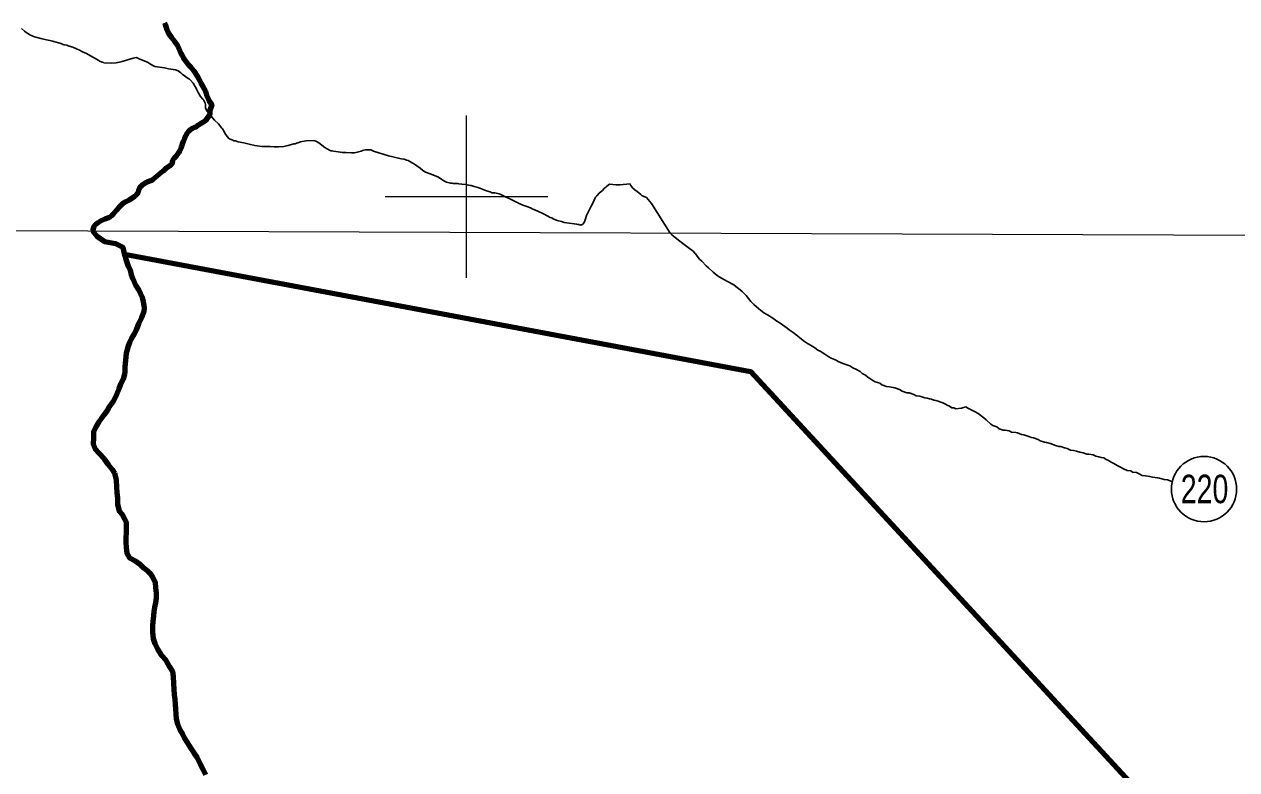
# Model space of a CAD drawing. Extents: x 553962 to 842807, y 8883888 to 9032388.
# Drawn here: x 644560 to 659476, y 8942952 to 8952120 of the extents above; entities that cross this region are included whole.
import ezdxf
from ezdxf.enums import TextEntityAlignment as Align

# ---------------------------------------------------------------- set-up
doc = ezdxf.new("R2010")
doc.units = 0
doc.header["$LTSCALE"] = 200
for name, color, linetype, lineweight in [('1', 7, 'Continuous', 13), ('12', 7, 'Continuous', 25), ('2', 7, 'Continuous', 13), ('24', 7, 'Continuous', 25), ('48', 7, 'Continuous', 25), ('9', 7, 'Continuous', 90)]:
    doc.layers.add(name, color=color, linetype=linetype, lineweight=lineweight)

msp = doc.modelspace()

# ---------------------------------------------------------------- linework, layer by layer
at = {"layer": '1'}
msp.add_line((565315.3, 8949866.8), (791497.7, 8949052.2), dxfattribs=at)
at = {"layer": '12'}
for points in [[(644525.6, 8952067.7), (644562.3, 8952035.3), (644585, 8952018.8), (644610.2, 8952003.3), (644630.2, 8951989.1), (644666.2, 8951972.1), (644686.9, 8951965), (644764.8, 8951944.4), (644796.3, 8951937.1)], [(644796.3, 8951937.1), (644909.5, 8951910.6), (644920.9, 8951908.3), (644925, 8951908), (644979.4, 8951891), (644998, 8951886), (645049.9, 8951868.9), (645083.2, 8951861.5), (645101.9, 8951853.7), (645139.4, 8951844.3), (645159.2, 8951837.9), (645204.5, 8951819), (645240.2, 8951802.2), (645277.4, 8951781.6), (645324.7, 8951759), (645344.3, 8951747.1), (645476.8, 8951676.5), (645486.1, 8951668), (645499.5, 8951664.1), (645517.2, 8951655.3), (645535.4, 8951649), (645539.2, 8951646.5), (645633, 8951642.2), (645691.3, 8951646.6), (645709.7, 8951650.6), (645730.5, 8951653.2), (645766.4, 8951661.2), (645899.9, 8951704.4), (645939.9, 8951711), (645983.5, 8951692.1)], [(645983.5, 8951692.1), (646075.3, 8951652.5), (646111.1, 8951629), (646148, 8951608.5), (646165.6, 8951600.8), (646285, 8951585.6), (646336.2, 8951574), (646420.6, 8951561.2), (646455.4, 8951547.2), (646471.8, 8951536), (646471.8, 8951536), (646486.8, 8951523.3), (646503.8, 8951505.7), (646575.7, 8951452.5), (646594.5, 8951444.4), (646606.7, 8951433.2), (646637.1, 8951396.7), (646646.8, 8951381.7), (646658, 8951359.9), (646668.8, 8951343), (646678.2, 8951321.5), (646688, 8951304.6), (646697.6, 8951280.8), (646727.3, 8951231.4), (646758, 8951198.7), (646768, 8951185.4), (646778.9, 8951166.6), (646784.6, 8951148.8), (646787.7, 8951132.6), (646791.2, 8951093), (646800.1, 8951065.2), (646806.8, 8951054.1), (646825.7, 8951029.2), (646836.3, 8951019.3)], [(646836.3, 8951019.3), (646900.5, 8950941.1), (646947.8, 8950893.8), (646989, 8950843.2), (646999.3, 8950832.7), (647020.7, 8950801.7), (647029.2, 8950781.7), (647056, 8950740.5), (647082.1, 8950712.4), (647088.1, 8950711.7), (647092.4, 8950707.5), (647124.6, 8950692.9), (647140, 8950688.1), (647158.6, 8950685.3), (647192, 8950676), (647261.7, 8950661.8), (647311.3, 8950649.3), (647341.4, 8950639.7), (647378.7, 8950633.5), (647398.1, 8950627.8), (647482.5, 8950615.3), (647499.6, 8950617.1), (647516.6, 8950616.2), (647534.4, 8950617.1), (647567, 8950615.2), (647584.8, 8950616), (647635.2, 8950612), (647686.3, 8950610.9), (647752.8, 8950616), (647787.8, 8950625.3), (647806.4, 8950629), (647874.6, 8950648.1), (647891.6, 8950651.4), (647907.9, 8950657.4), (647927.3, 8950661.4), (647959.8, 8950672.6), (647976.9, 8950676.8), (648028, 8950685.3), (648114.8, 8950689.6), (648132.7, 8950687.8), (648148.1, 8950682.9)], [(648148.1, 8950682.9), (648164.7, 8950675), (648182.5, 8950661), (648182.5, 8950661), (648220.1, 8950634.8), (648256.1, 8950605.6), (648313.6, 8950571.5), (648330.6, 8950564.1), (648347.6, 8950561.8), (648365.5, 8950557.5), (648449.1, 8950549.1), (648469.5, 8950544.6), (648518.1, 8950542.6), (648584.7, 8950537.4), (648618.8, 8950538.4), (648656, 8950545.3), (648704, 8950560.3), (648722.7, 8950568.1), (648755.2, 8950574.3), (648790.8, 8950577.7), (648823.9, 8950574.6), (648830.2, 8950570.4), (648856.3, 8950558.2), (649040.7, 8950501.6), (649162.3, 8950475.3), (649195.7, 8950466.1), (649232.2, 8950461.1), (649246.8, 8950457.3), (649263.9, 8950450), (649281.7, 8950444.2), (649302.8, 8950433.5), (649338.4, 8950412.6), (649353.4, 8950402.1), (649372.5, 8950392.3), (649390.3, 8950378.1), (649429.6, 8950352.4), (649463.8, 8950322.8)], [(649463.8, 8950322.8), (649496, 8950302.2), (649566.4, 8950276.3), (649656.2, 8950238.2), (649697.2, 8950209.8), (649723.5, 8950193.7), (649754.2, 8950177.4), (649803.5, 8950168), (649822.1, 8950166.5), (649838.4, 8950163.6), (649890.3, 8950161.1), (649908.1, 8950157), (649941.4, 8950154.8), (649991, 8950148.7), (650043.7, 8950137.9), (650060, 8950135.7), (650094.1, 8950124.2), (650129.7, 8950116.2), (650163, 8950105.8), (650246.8, 8950073.4), (650290.2, 8950059), (650299.6, 8950053.7), (650314, 8950049.1), (650350.6, 8950046.1), (650401.7, 8950034.4), (650423.7, 8950025.5), (650495.5, 8949988.7), (650527.2, 8949975.8), (650567.9, 8949956.7), (650647.1, 8949916), (650692.9, 8949894.2), (650744.7, 8949878.8), (650786.2, 8949862.9), (650817.8, 8949847.6), (650868.1, 8949827.7), (650955.7, 8949785.1), (651029.6, 8949745.1), (651050.4, 8949738.1), (651068, 8949728), (651116.1, 8949708.1), (651168, 8949695.8), (651202.9, 8949684), (651236.2, 8949676.7), (651354.7, 8949662.8), (651372.6, 8949657.6), (651386.2, 8949655.9), (651395.9, 8949651.2), (651408.9, 8949652.2), (651421.4, 8949655), (651431.1, 8949662), (651447.1, 8949681.5), (651460.4, 8949714.1), (651478.1, 8949766.7), (651536.2, 8949883), (651545, 8949904.7), (651589.1, 8949992.5), (651602.4, 8950009.9), (651633.8, 8950042.4), (651659.3, 8950063.8), (651672.2, 8950077.6), (651695.1, 8950098.5), (651713.6, 8950118.7), (651719.4, 8950120.8), (651727.6, 8950129), (651743.7, 8950140.7)], [(651743.7, 8950140.7), (651759.9, 8950152.4), (651841.5, 8950147.5), (651886.8, 8950146.4), (652015.9, 8950156.6)], [(652015.9, 8950156.6), (652017.2, 8950142.2), (652048.2, 8950106.5), (652073.3, 8950084.6), (652100.6, 8950064.8), (652145.1, 8950025.5), (652162.5, 8950012.1), (652213.7, 8949988.4), (652275.7, 8949914.2), (652507.9, 8949552.8)], [(652507.9, 8949552.8), (652526.9, 8949530.3), (652569.2, 8949497.5), (652626.3, 8949452.1), (652693.5, 8949399.1), (652728.3, 8949373.8), (652790.5, 8949328.3), (652815.3, 8949300.6), (652867.3, 8949232.7), (652894.6, 8949204.9), (652949.2, 8949149.5), (652979, 8949124.3), (653033.6, 8949071.3), (653085.8, 8949030.9), (653110.7, 8949013.2), (653173, 8948977.8), (653212.8, 8948957.5), (653287.6, 8948916.9), (653314.9, 8948894.2), (653367.1, 8948853.8), (653392, 8948833.6), (653441.6, 8948785.7)], [(653441.6, 8948785.7), (653498.6, 8948710.3), (653535.8, 8948672.5), (653595.5, 8948622), (653660.1, 8948571.5), (653702.4, 8948546.2), (653779.6, 8948498.1), (653804.4, 8948477.9), (653859.2, 8948442.5), (653889.1, 8948422.3), (653946.3, 8948381.8), (653971.1, 8948361.6), (654018.4, 8948328.8), (654070.6, 8948288.4), (654100.4, 8948263.2), (654160.1, 8948220.2), (654195, 8948194.9), (654262.2, 8948156.9), (654284.6, 8948141.8), (654324.4, 8948114), (654351.8, 8948098.8), (654409.1, 8948063.3), (654458.8, 8948030.5), (654488.7, 8948015.2), (654548.5, 8947987.3), (654573.4, 8947972.1), (654628.3, 8947946.7), (654655.7, 8947941.5), (654718.1, 8947918.6), (654752.9, 8947893.3), (654800.3, 8947875.5), (654842.6, 8947850.2), (654867.5, 8947825), (654909.8, 8947804.7), (654937.1, 8947779.4), (654999.3, 8947739), (655026.8, 8947723.8), (655084.1, 8947705.9), (655111.5, 8947685.7), (655168.9, 8947665.2), (655203.9, 8947662.5), (655268.8, 8947647.1), (655328.6, 8947626.6), (655358.5, 8947606.4), (655415.9, 8947588.5), (655445.9, 8947588.3), (655505.8, 8947565.4), (655533.2, 8947550.2), (655578.2, 8947547.4), (655600.6, 8947539.7), (655640.5, 8947524.4), (655668, 8947521.8), (655698, 8947514), (655720.4, 8947511.4), (655747.8, 8947496.2), (655772.8, 8947493.5), (655802.8, 8947483.3), (655835.2, 8947473.1), (655860.1, 8947462.9), (655892.6, 8947450.2), (655915, 8947435), (655942.4, 8947424.8), (655969.7, 8947404.6), (655997.2, 8947401.9), (656019.7, 8947391.7), (656089.8, 8947398.8)], [(656089.8, 8947398.8), (656144.9, 8947413.4), (656177.2, 8947393.2), (656259.5, 8947355.1), (656294.3, 8947332.3), (656364, 8947281.8), (656393.8, 8947254.1), (656450.9, 8947201.1), (656475.8, 8947185.9), (656523.2, 8947168.1), (656553, 8947145.4), (656602.9, 8947127.5), (656627.9, 8947127.3), (656675.4, 8947119.5), (656705.3, 8947104.3), (656757.8, 8947101.5), (656780.2, 8947093.8), (656830.1, 8947073.4), (656857.6, 8947070.8), (656907.5, 8947055.4), (656952.4, 8947040.1), (656977.4, 8947034.9), (657032.2, 8947012), (657059.6, 8946996.8), (657112, 8946978.9), (657137, 8946978.8), (657199.4, 8946960.8), (657234.3, 8946943.1), (657289.2, 8946927.7), (657311.7, 8946927.6), (657356.6, 8946912.2), (657391.6, 8946904.5), (657431.4, 8946884.2), (657466.4, 8946879), (657506.4, 8946871.2), (657546.3, 8946858.4), (657586.2, 8946850.6), (657631.1, 8946835.3), (657656.1, 8946832.6), (657708.6, 8946824.8), (657741, 8946807.1), (657781, 8946801.8), (657808.4, 8946794.1), (657840.9, 8946788.9), (657868.2, 8946768.7), (657898.1, 8946753.4), (657930.5, 8946735.7), (657965.4, 8946717.9), (658005.2, 8946692.6), (658045.1, 8946672.3), (658085, 8946652.1), (658129.8, 8946634.2), (658172.3, 8946628.9), (658194.7, 8946611.3), (658242.2, 8946608.4), (658277.1, 8946590.7), (658314.5, 8946572.9), (658354.4, 8946567.7), (658406.9, 8946559.8), (658439.3, 8946552.1), (658501.8, 8946544.2), (658524.3, 8946536.5), (658556.7, 8946531.3), (658581.7, 8946523.6), (658624.1, 8946515.8), (658678.1, 8946495.9)]]:
    msp.add_lwpolyline(points, dxfattribs=at)
at = {"layer": '2'}
for p, q in [((650000, 8949000), (650000, 8951000)), ((649000, 8950000), (651000, 8950000))]:
    msp.add_line(p, q, dxfattribs=at)
at = {"layer": '24', "lineweight": 53}
for points in [[(646283.8, 8952137.9), (646294.2, 8952117.2), (646303.6, 8952093.2), (646314.2, 8952051.4), (646322.1, 8952031.6), (646333.3, 8952009.5), (646371.8, 8951955.7), (646409.8, 8951910.5), (646439.8, 8951866.6), (646450.5, 8951847.3), (646458, 8951830.6), (646472.5, 8951791.1), (646486.6, 8951759.9), (646498.1, 8951747.5), (646499.4, 8951739.7), (646505.1, 8951731.6), (646514.5, 8951713), (646583.4, 8951618.5), (646609.2, 8951590.9), (646641.2, 8951551.7), (646693.7, 8951470.3), (646714.7, 8951432.5), (646733, 8951394), (646757.5, 8951355.4), (646787.6, 8951297.6), (646794.5, 8951277.6), (646802.9, 8951258.2), (646813.5, 8951223.4), (646828.6, 8951181.9), (646867.6, 8951129.6), (646843.9, 8951061.1), (646845, 8951008.9), (646791.1, 8950934.1), (646683.1, 8950866.1), (646677.6, 8950858.9), (646671.1, 8950853.6), (646653.5, 8950848.9), (646638.2, 8950843.1), (646630.5, 8950838.5), (646616.1, 8950832.7), (646599.8, 8950823.2), (646580.2, 8950802.2), (646561.5, 8950775.5), (646560.4, 8950771.5), (646555.5, 8950768.2), (646542.3, 8950744.3), (646531.8, 8950710), (646515, 8950677.7), (646512.5, 8950667.1), (646506.4, 8950657.3), (646501.5, 8950645.9), (646497.6, 8950630.7), (646492.6, 8950619.9), (646490.9, 8950607.9), (646484.9, 8950590.5), (646469.4, 8950559.1), (646462.5, 8950548.1), (646458, 8950536.5), (646432.8, 8950502.7), (646402.4, 8950473.1), (646389.6, 8950454.9), (646380.3, 8950433.1), (646383.9, 8950415.2), (646358.3, 8950385.9), (646349.6, 8950380.1), (646346.8, 8950375.3), (646301.4, 8950345.1), (646282.4, 8950327.6), (646263.6, 8950315.1), (646191.8, 8950251), (646140.7, 8950210.9), (646124.2, 8950199.9), (646066.5, 8950178.1), (646011.5, 8950140), (645996.7, 8950128.3), (645982.6, 8950114.3), (645972, 8950100.3), (645964.6, 8950078.7), (645959.7, 8950055.9), (645950.6, 8950035.7), (645935.3, 8950018), (645917.5, 8950001), (645852.5, 8949956.4), (645811.5, 8949936.1), (645770.2, 8949910.8), (645755.5, 8949898), (645724.3, 8949866.7), (645691.2, 8949830.5), (645653.7, 8949784.5), (645634.4, 8949765.2), (645614.7, 8949747.7), (645596.6, 8949739.8), (645549.2, 8949723.6), (645488.8, 8949693.4), (645467.8, 8949680.1), (645433.2, 8949653.7), (645415.9, 8949633.6), (645398.8, 8949579.9)], [(645398.8, 8949579.9), (645451.4, 8949513.8), (645546.2, 8949449.6), (645683.8, 8949425.1), (645771.3, 8949377.1), (645790.9, 8949299.5), (645808.1, 8949229.4), (645840.2, 8949144.1), (645862.5, 8949099), (645877.2, 8949041.4), (645894.5, 8948988.8), (645929.2, 8948913.5), (645968.9, 8948848.3), (645990.2, 8948804.6)], [(645990.2, 8948804.6), (646010.9, 8948758.1), (646021.2, 8948711.7), (646036.8, 8948634.2), (646031.6, 8948582.6), (646000.6, 8948510.3), (645964.4, 8948438), (645936.5, 8948358.1), (645911.3, 8948313.2), (645873.5, 8948253.4), (645853.2, 8948208.5), (645832.9, 8948151), (645815.1, 8948076.1), (645807.1, 8947983.6), (645799.2, 8947908.6), (645796.4, 8947834.9)], [(645796.4, 8947834.9), (645776, 8947756.1), (645745.7, 8947693.7), (645725.4, 8947636.3), (645695.1, 8947568.9), (645674.8, 8947521.4), (645649.6, 8947474), (645596.7, 8947399.3), (645571.5, 8947356.9), (645541.2, 8947317), (645511, 8947272.1), (645475.8, 8947229.8), (645437.9, 8947162.4), (645412.7, 8947110), (645409.8, 8947032.5), (645409.4, 8946954.9), (645431.6, 8946894.8), (645476.4, 8946847), (645541.1, 8946774.1), (645593.3, 8946706.3), (645643.1, 8946643.5), (645668.8, 8946601.4)], [(645668.8, 8946601.4), (645692.5, 8946518.2), (645694.6, 8946428.1), (645699.3, 8946363), (645706.4, 8946292.9), (645706.1, 8946220.4), (645728.2, 8946132.7), (645765.5, 8946092.5), (645792.8, 8946037.3), (645812.6, 8945992.2), (645814.8, 8945939.6), (645812, 8945874.6), (645809.1, 8945802.1), (645808.9, 8945752), (645813.6, 8945684.5), (645820.8, 8945616.9), (645855.5, 8945556.7), (645925.1, 8945520.2)], [(645925.1, 8945520.2), (645980.3, 8945480.9), (646030.3, 8945430.9), (646080.3, 8945396.3), (646111.1, 8945361.7), (646137.1, 8945322.6), (646171.8, 8945257.3), (646176.4, 8945189.8), (646181.1, 8945124.7), (646180.8, 8945062.1), (646173.1, 8945007.1), (646162.8, 8944947.2), (646155, 8944897.2), (646149.8, 8944847.1), (646141.9, 8944777.1), (646139.2, 8944722.1), (646138.8, 8944644.6), (646145.9, 8944567), (646168.2, 8944506.8), (646200.3, 8944434.1), (646247.5, 8944358.8), (646299.8, 8944301), (646309, 8944284.7)], [(646309, 8944284.7), (646346.9, 8944218.2), (646384.2, 8944160.4), (646391.3, 8944097.8), (646395.9, 8944012.8), (646398.1, 8943942.7), (646405.3, 8943872.6), (646412.5, 8943820), (646414.7, 8943755), (646419.5, 8943702.4), (646424.2, 8943637.3), (646428.9, 8943577.3), (646446.1, 8943512.1), (646475.8, 8943444.4), (646508, 8943389.2), (646527.8, 8943344.1), (646562.6, 8943288.9), (646604.8, 8943221.1), (646647, 8943160.8), (646684.3, 8943105.6), (646721.5, 8943027.8), (646756.1, 8942957.6), (646790.8, 8942889.9)]]:
    msp.add_lwpolyline(points, dxfattribs=at)
at = {"layer": '48'}
msp.add_circle((659073.8, 8946403.8), 401.3, dxfattribs=at)
at = {"layer": '9'}
for points in [[(646283.8, 8952137.9), (646294.2, 8952117.2), (646303.6, 8952093.2), (646314.2, 8952051.4), (646322.1, 8952031.6), (646333.3, 8952009.5), (646371.8, 8951955.7), (646409.8, 8951910.5), (646439.8, 8951866.6), (646450.5, 8951847.3), (646458, 8951830.6), (646472.5, 8951791.1), (646486.6, 8951759.9), (646498.1, 8951747.5), (646499.4, 8951739.7), (646505.1, 8951731.6), (646514.5, 8951713), (646583.4, 8951618.5), (646609.2, 8951590.9), (646641.2, 8951551.7), (646693.7, 8951470.3), (646714.7, 8951432.5), (646733, 8951394), (646757.5, 8951355.4), (646787.6, 8951297.6), (646794.5, 8951277.6), (646802.9, 8951258.2), (646813.5, 8951223.4), (646828.6, 8951181.9), (646867.6, 8951129.6), (646843.9, 8951061.1), (646845, 8951008.9), (646791.1, 8950934.1), (646683.1, 8950866.1), (646677.6, 8950858.9), (646671.1, 8950853.6), (646653.5, 8950848.9), (646638.2, 8950843.1), (646630.5, 8950838.5), (646616.1, 8950832.7), (646599.8, 8950823.2), (646580.2, 8950802.2), (646561.5, 8950775.5), (646560.4, 8950771.5), (646555.5, 8950768.2), (646542.3, 8950744.3), (646531.8, 8950710), (646515, 8950677.7), (646512.5, 8950667.1), (646506.4, 8950657.3), (646501.5, 8950645.9), (646497.6, 8950630.7), (646492.6, 8950619.9), (646490.9, 8950607.9), (646484.9, 8950590.5), (646469.4, 8950559.1), (646462.5, 8950548.1), (646458, 8950536.5), (646432.8, 8950502.7), (646402.4, 8950473.1), (646389.6, 8950454.9), (646380.3, 8950433.1), (646383.9, 8950415.2), (646358.3, 8950385.9), (646349.6, 8950380.1), (646346.8, 8950375.3), (646301.4, 8950345.1), (646282.4, 8950327.6), (646263.6, 8950315.1), (646191.8, 8950251), (646140.7, 8950210.9), (646124.2, 8950199.9), (646066.5, 8950178.1), (646011.5, 8950140), (645996.7, 8950128.3), (645982.6, 8950114.3), (645972, 8950100.3), (645964.6, 8950078.7), (645959.7, 8950055.9), (645950.6, 8950035.7), (645935.3, 8950018), (645917.5, 8950001), (645852.5, 8949956.4), (645811.5, 8949936.1), (645770.2, 8949910.8), (645755.5, 8949898), (645724.3, 8949866.7), (645691.2, 8949830.5), (645653.7, 8949784.5), (645634.4, 8949765.2), (645614.7, 8949747.7), (645596.6, 8949739.8), (645549.2, 8949723.6), (645488.8, 8949693.4), (645467.8, 8949680.1), (645433.2, 8949653.7), (645415.9, 8949633.6), (645398.8, 8949579.9)], [(645398.8, 8949579.9), (645451.4, 8949513.8), (645546.2, 8949449.6), (645683.8, 8949425.1), (645771.3, 8949377.1), (645790.9, 8949299.5), (645808.1, 8949229.4), (645840.2, 8949144.1), (645862.5, 8949099), (645877.2, 8949041.4), (645894.5, 8948988.8), (645929.2, 8948913.5), (645968.9, 8948848.3), (645990.2, 8948804.6)], [(645793.1, 8949290.9), (653495.4, 8947850), (659002.1, 8941889), (662654, 8939737.7), (668185.2, 8933928.8)], [(645990.2, 8948804.6), (646010.9, 8948758.1), (646021.2, 8948711.7), (646036.8, 8948634.2), (646031.6, 8948582.6), (646000.6, 8948510.3), (645964.4, 8948438), (645936.5, 8948358.1), (645911.3, 8948313.2), (645873.5, 8948253.4), (645853.2, 8948208.5), (645832.9, 8948151), (645815.1, 8948076.1), (645807.1, 8947983.6), (645799.2, 8947908.6), (645796.4, 8947834.9)], [(645796.4, 8947834.9), (645776, 8947756.1), (645745.7, 8947693.7), (645725.4, 8947636.3), (645695.1, 8947568.9), (645674.8, 8947521.4), (645649.6, 8947474), (645596.7, 8947399.3), (645571.5, 8947356.9), (645541.2, 8947317), (645511, 8947272.1), (645475.8, 8947229.8), (645437.9, 8947162.4), (645412.7, 8947110), (645409.8, 8947032.5), (645409.4, 8946954.9), (645431.6, 8946894.8), (645476.4, 8946847), (645541.1, 8946774.1), (645593.3, 8946706.3), (645643.1, 8946643.5), (645668.8, 8946601.4)], [(645668.8, 8946601.4), (645692.5, 8946518.2), (645694.6, 8946428.1), (645699.3, 8946363), (645706.4, 8946292.9), (645706.1, 8946220.4), (645728.2, 8946132.7), (645765.5, 8946092.5), (645792.8, 8946037.3), (645812.6, 8945992.2), (645814.8, 8945939.6), (645812, 8945874.6), (645809.1, 8945802.1), (645808.9, 8945752), (645813.6, 8945684.5), (645820.8, 8945616.9), (645855.5, 8945556.7), (645925.1, 8945520.2)], [(645925.1, 8945520.2), (645980.3, 8945480.9), (646030.3, 8945430.9), (646080.3, 8945396.3), (646111.1, 8945361.7), (646137.1, 8945322.6), (646171.8, 8945257.3), (646176.4, 8945189.8), (646181.1, 8945124.7), (646180.8, 8945062.1), (646173.1, 8945007.1), (646162.8, 8944947.2), (646155, 8944897.2), (646149.8, 8944847.1), (646141.9, 8944777.1), (646139.2, 8944722.1), (646138.8, 8944644.6), (646145.9, 8944567), (646168.2, 8944506.8), (646200.3, 8944434.1), (646247.5, 8944358.8), (646299.8, 8944301), (646309, 8944284.7)], [(646309, 8944284.7), (646346.9, 8944218.2), (646384.2, 8944160.4), (646391.3, 8944097.8), (646395.9, 8944012.8), (646398.1, 8943942.7), (646405.3, 8943872.6), (646412.5, 8943820), (646414.7, 8943755), (646419.5, 8943702.4), (646424.2, 8943637.3), (646428.9, 8943577.3), (646446.1, 8943512.1), (646475.8, 8943444.4), (646508, 8943389.2), (646527.8, 8943344.1), (646562.6, 8943288.9), (646604.8, 8943221.1), (646647, 8943160.8), (646684.3, 8943105.6), (646721.5, 8943027.8), (646756.1, 8942957.6), (646790.8, 8942889.9)]]:
    msp.add_lwpolyline(points, dxfattribs=at)
msp.add_spline([(637260.6, 8972975.8), (641524.5, 8971056.2), (652526.1, 8965412.7), (653164.3, 8965062.8), (670790.5, 8953770.1), (686194, 8943929.9), (696283.3, 8937647.1)], degree=3, dxfattribs=at)

# ---------------------------------------------------------------- texts
at = {"layer": '48', "width": 0.75}
msp.add_text('220', height=350, dxfattribs=at).set_placement((659080.5, 8946230.4), align=Align.CENTER)

doc.saveas('drawing.dxf')
